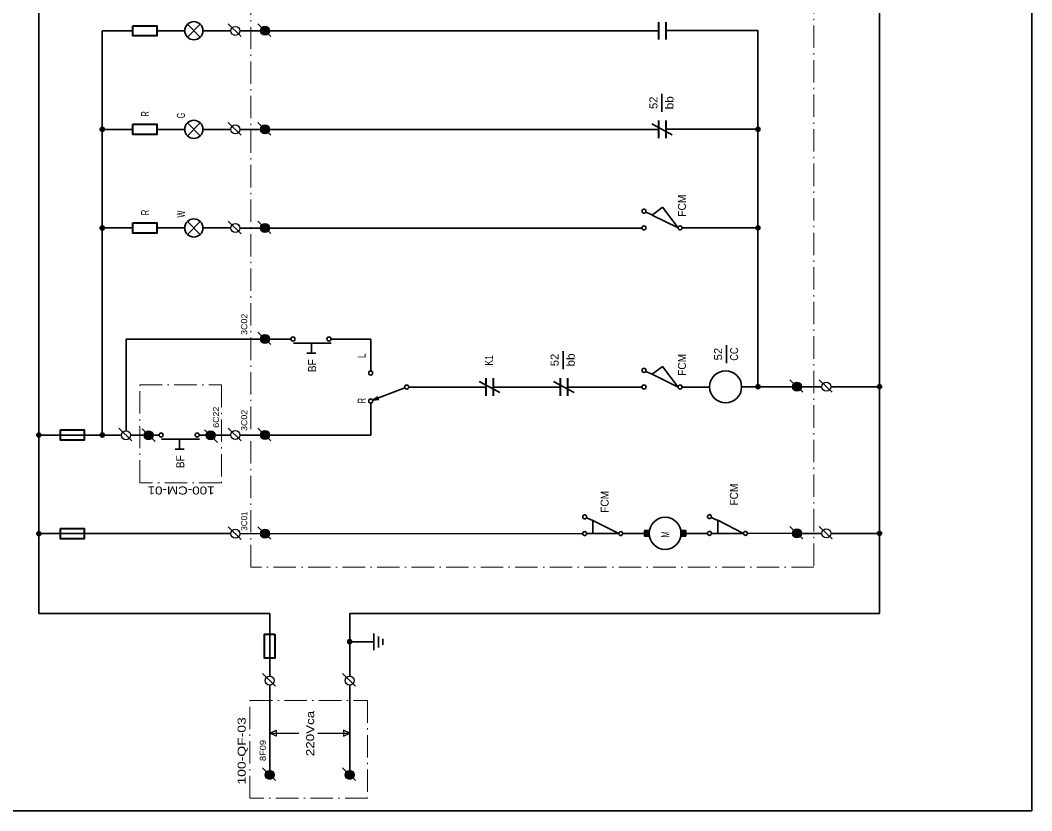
# Model space of a CAD drawing. Extents: x -4160 to -2690, y -474 to 714.
# Drawn here: x -3877.1 to -3750.8, y -166.5 to -67.8 of the extents above; entities that cross this region are included whole.
import ezdxf
from ezdxf.enums import TextEntityAlignment as Align

# ---------------------------------------------------------------- set-up
doc = ezdxf.new("R2010")
doc.units = 0
doc.header["$LTSCALE"] = 0.56
doc.linetypes.add('DOT_DASHED', pattern=[7.7, 5, -1.2, 0.3, -1.2])
for name, color, linetype, lineweight in [('1', 7, 'Continuous', 25), ('2', 7, 'Continuous', 25), ('4', 7, 'Continuous', 25), ('5', 7, 'Continuous', 35)]:
    doc.layers.add(name, color=color, linetype=linetype, lineweight=lineweight)

msp = doc.modelspace()

# ---------------------------------------------------------------- hatches: boundary and pattern name
at = {"layer": '1'}
for points in [[(-3846.5451, -69.6769, 1), (-3846.5451, -68.553, 1)], [(-3866.8755, -81.1668, 1), (-3866.8755, -81.6825, 1)], [(-3846.5451, -81.9931, 1), (-3846.5451, -80.8693, 1)], [(-3784.9703, -81.153, 1), (-3784.9703, -81.6687, 1)], [(-3866.8756, -93.483, 1), (-3866.8756, -93.9987, 1)], [(-3846.5452, -94.3094, 1), (-3846.5452, -93.1855, 1)], [(-3784.9704, -93.4692, 1), (-3784.9704, -93.9849, 1)], [(-3846.5452, -108.1702, 1), (-3846.5452, -107.0463, 1)], [(-3784.9704, -113.3048, 1), (-3784.9704, -113.8205, 1)], [(-3780.0915, -114.1247, 1), (-3780.0915, -113.0008, 1)], [(-3769.7833, -113.3048, 1), (-3769.7833, -113.8205, 1)], [(-3874.7921, -119.3374, 1), (-3874.7921, -119.8531, 1)], [(-3866.8756, -119.3374, 1), (-3866.8756, -119.8531, 1)], [(-3861.0915, -120.1947, 1), (-3861.0915, -119.0708, 1)], [(-3853.3283, -120.1947, 1), (-3853.3283, -119.0708, 1)], [(-3846.5452, -120.1638, 1), (-3846.5452, -119.0399, 1)], [(-3846.5452, -132.48, 1), (-3846.5452, -131.3562, 1)], [(-3780.0915, -132.4377, 1), (-3780.0915, -131.3139, 1)], [(-3874.7921, -131.6537, 1), (-3874.7921, -132.1694, 1)], [(-3798.5379, -132.2246), (-3798.5379, -131.5239), (-3799.1451, -131.5239), (-3799.1451, -132.2246)], [(-3794.5917, -132.2246), (-3794.5917, -131.5239), (-3793.9845, -131.5239), (-3793.9845, -132.2246)], [(-3769.7833, -131.6178, 1), (-3769.7833, -132.1335, 1)], [(-3835.9574, -145.1596, 1), (-3835.9574, -145.6753, 1)], [(-3845.9574, -162.5966, 1), (-3845.9574, -161.4728, 1)], [(-3835.9574, -162.5966, 1), (-3835.9574, -161.4728, 1)]]:
    msp.add_hatch(color=256, dxfattribs=at).paths.add_polyline_path(points)

# ---------------------------------------------------------------- linework, layer by layer
at = {"layer": '1', "lineweight": 35}
for p, q in [((-3874.7921, -141.8757), (-3874.7921, -62.7685)), ((-3769.7833, -62.7685), (-3769.7833, -141.8757)), ((-3866.8756, -119.5953), (-3866.8755, -69.1084)), ((-3866.8755, -69.1084), (-3863.0503, -69.1084)), ((-3860.0625, -69.1084), (-3856.5624, -69.1084)), ((-3854.3024, -69.1084), (-3850.8023, -69.1084)), ((-3851.1359, -68.2551), (-3849.5129, -69.8287)), ((-3849.6785, -69.1166), (-3797.3429, -69.1166)), ((-3847.4406, -68.2453), (-3845.8175, -69.8189)), ((-3796.4349, -69.0946), (-3784.9703, -69.0945)), ((-3784.9703, -113.5627), (-3784.9703, -69.0945)), ((-3796.9667, -79.2431), (-3796.9667, -77.0006)), ((-3851.1359, -80.5714), (-3849.5129, -82.145)), ((-3847.4407, -80.5616), (-3845.8176, -82.1352)), ((-3798.216, -80.7443), (-3795.6718, -82.1213)), ((-3866.8755, -81.4247), (-3863.0504, -81.4247)), ((-3860.0625, -81.4247), (-3856.5625, -81.4247)), ((-3854.3025, -81.4247), (-3850.8023, -81.4247)), ((-3849.6785, -81.4329), (-3797.3429, -81.4329)), ((-3796.4349, -81.4109), (-3784.9703, -81.4109)), ((-3798.1685, -92.1151), (-3798.9689, -91.7667)), ((-3851.136, -92.8877), (-3849.5129, -94.4613)), ((-3847.4407, -92.8779), (-3845.8177, -94.4515)), ((-3866.8755, -93.7409), (-3863.0505, -93.7409)), ((-3860.0625, -93.7409), (-3856.5625, -93.7409)), ((-3854.3025, -93.7409), (-3850.8024, -93.7409)), ((-3849.6786, -93.7491), (-3799.4429, -93.7491)), ((-3794.4439, -93.7271), (-3784.9703, -93.7271)), ((-3847.4407, -106.7387), (-3845.8177, -108.3123)), ((-3863.9005, -119.0579), (-3863.9004, -107.6099)), ((-3863.9004, -107.6099), (-3843.2997, -107.6099)), ((-3843.0023, -108.1165), (-3838.2748, -108.1165)), ((-3840.7435, -108.1165), (-3840.7435, -109.3699)), ((-3833.3419, -107.6099), (-3838.1875, -107.6099)), ((-3833.3419, -107.6099), (-3833.3419, -111.6107)), ((-3788.8891, -110.6293), (-3788.8891, -108.3868)), ((-3841.3082, -109.3699), (-3840.1789, -109.3699)), ((-3809.3105, -111.3629), (-3809.3105, -109.1203)), ((-3798.1685, -111.9947), (-3798.9689, -111.6464)), ((-3833.1089, -115.2622), (-3829.0751, -113.6971)), ((-3828.592, -113.6067), (-3818.9003, -113.6067)), ((-3819.7735, -112.9182), (-3817.2293, -114.2952)), ((-3817.9923, -113.6067), (-3809.6131, -113.6067)), ((-3810.4863, -112.9182), (-3807.9421, -114.2952)), ((-3799.4439, -113.6067), (-3808.7051, -113.6067)), ((-3794.4439, -113.6067), (-3791.0053, -113.6067)), ((-3787.0074, -113.5627), (-3780.6535, -113.5627)), ((-3780.9871, -112.6931), (-3779.364, -114.2667)), ((-3779.5295, -113.5627), (-3776.9887, -113.5627)), ((-3777.3223, -112.6931), (-3775.6993, -114.2667)), ((-3775.8649, -113.5627), (-3769.7833, -113.5627)), ((-3833.1089, -115.2622), (-3832.4629, -114.8225)), ((-3833.3419, -119.6035), (-3833.3419, -115.6027)), ((-3833.1089, -115.2622), (-3832.3354, -115.1512)), ((-3864.796, -118.7503), (-3863.1729, -120.3239)), ((-3851.1361, -118.7339), (-3849.513, -120.3075)), ((-3847.4407, -118.7323), (-3845.8177, -120.3059)), ((-3874.7921, -119.5953), (-3864.4621, -119.5953)), ((-3863.3387, -119.6035), (-3859.766, -119.6035)), ((-3861.8715, -118.8313), (-3860.2485, -120.4049)), ((-3854.7661, -119.6035), (-3850.8025, -119.6035)), ((-3852.4969, -120.5346), (-3854.12, -118.961)), ((-3849.6786, -119.6035), (-3833.3419, -119.6035)), ((-3859.4686, -120.1101), (-3854.7411, -120.1101)), ((-3856.6509, -120.1101), (-3857.5589, -120.1101)), ((-3857.2099, -120.1101), (-3857.2099, -121.3634)), ((-3857.7745, -121.3634), (-3856.6452, -121.3634)), ((-3805.5801, -130.2858), (-3806.3804, -129.9375)), ((-3789.9988, -130.2638), (-3790.7991, -129.9155)), ((-3851.136, -131.0583), (-3849.5129, -132.6319)), ((-3847.4407, -131.0485), (-3845.8177, -132.6221)), ((-3780.9871, -131.0062), (-3779.364, -132.5798)), ((-3777.3223, -131.0061), (-3775.6993, -132.5797)), ((-3874.7921, -131.9115), (-3850.8024, -131.9115)), ((-3849.6786, -131.9197), (-3806.7821, -131.8978)), ((-3805.5801, -131.8978), (-3806.3554, -131.8978)), ((-3798.5638, -131.8758), (-3801.8555, -131.8758)), ((-3794.5658, -131.8758), (-3791.2741, -131.8758)), ((-3789.9988, -131.8758), (-3790.7741, -131.8758)), ((-3786.2741, -131.8539), (-3780.6535, -131.8758)), ((-3779.5295, -131.8758), (-3776.9887, -131.8758)), ((-3775.8649, -131.8757), (-3769.7833, -131.8757)), ((-3874.7921, -141.8757), (-3845.9573, -141.8757)), ((-3845.9573, -141.8757), (-3845.9573, -149.6963)), ((-3835.9573, -141.8757), (-3835.9573, -149.6963)), ((-3835.9573, -141.8757), (-3769.7833, -141.8757)), ((-3832.9337, -146.4479), (-3832.9337, -144.387)), ((-3832.3831, -146.1329), (-3832.3831, -144.7396)), ((-3831.8035, -145.8136), (-3831.8035, -145.0589)), ((-3835.9573, -145.4175), (-3832.9337, -145.4175)), ((-3846.8529, -149.3887), (-3845.2299, -150.9623)), ((-3836.8529, -149.3887), (-3835.2299, -150.9623)), ((-3845.9574, -150.8202), (-3845.9574, -161.4727)), ((-3835.9574, -150.8202), (-3835.9574, -161.4727)), ((-3846.8529, -161.1651), (-3845.2299, -162.7387)), ((-3836.8529, -161.1651), (-3835.2299, -162.7387))]:
    msp.add_line(p, q, dxfattribs=at)
at = {"layer": '1', "lineweight": 40}
for p, q in [((-3797.3429, -70.2118), (-3797.3429, -68.0252)), ((-3796.4349, -70.2118), (-3796.4349, -68.0252)), ((-3797.3429, -82.5281), (-3797.3429, -80.3415)), ((-3796.4349, -82.5281), (-3796.4349, -80.3415)), ((-3818.9003, -114.7019), (-3818.9003, -112.5153)), ((-3817.9923, -114.7019), (-3817.9923, -112.5153)), ((-3809.6131, -114.7019), (-3809.6131, -112.5153)), ((-3808.7051, -114.7019), (-3808.7051, -112.5153))]:
    msp.add_line(p, q, dxfattribs=at)
at = {"layer": '1'}
for p, q in [((-3856.2315, -68.3093), (-3854.6333, -69.9075)), ((-3856.2315, -69.9075), (-3854.6334, -68.3094)), ((-3856.2315, -80.6256), (-3854.6334, -82.2237)), ((-3856.2315, -82.2237), (-3854.6335, -80.6257)), ((-3856.2315, -92.9419), (-3854.6335, -94.5399)), ((-3856.2315, -94.5399), (-3854.6335, -92.9419)), ((-3845.9573, -156.8151), (-3842.3215, -156.8151)), ((-3839.9376, -156.8151), (-3835.9573, -156.8151))]:
    msp.add_line(p, q, dxfattribs=at)
at = {"layer": '1', "linetype": 'DOT_DASHED', "lineweight": 13}
for points in [[(-3848.3279, -136.1027), (-3848.3279, 47.9667), (-3777.9927, 47.9667), (-3777.9927, -136.1027)], [(-3862.1888, -125.5548), (-3862.1888, -113.3493), (-3851.9577, -113.3492), (-3851.9577, -125.5548)], [(-3848.4239, -164.9458), (-3848.4239, -152.7493), (-3833.7453, -152.7493), (-3833.7453, -164.9458)]]:
    msp.add_lwpolyline(points, close=True, dxfattribs=at)
at = {"layer": '1', "lineweight": 40}
for points in [[(-3863.0503, -68.4785), (-3860.0625, -68.4785), (-3860.0625, -69.7383), (-3863.0503, -69.7383)], [(-3863.0504, -80.7948), (-3860.0625, -80.7948), (-3860.0625, -82.0545), (-3863.0504, -82.0545)], [(-3863.0505, -93.1111), (-3860.0625, -93.1111), (-3860.0625, -94.3707), (-3863.0505, -94.3707)], [(-3872.1015, -118.9655), (-3869.1136, -118.9655), (-3869.1136, -120.2251), (-3872.1015, -120.2251)], [(-3872.1015, -131.2817), (-3869.1136, -131.2817), (-3869.1136, -132.5414), (-3872.1015, -132.5414)], [(-3845.3275, -144.47), (-3845.3275, -147.4579), (-3846.5872, -147.4579), (-3846.5872, -144.47)]]:
    msp.add_lwpolyline(points, close=True, dxfattribs=at)
at = {"layer": '1', "lineweight": 35}
for points in [[(-3796.8791, -91.1477), (-3798.1857, -92.1279), (-3794.9439, -93.7271)], [(-3796.8791, -111.0273), (-3798.1857, -112.0076), (-3794.9439, -113.6067)], [(-3805.5801, -131.8978), (-3805.5801, -130.2643), (-3802.3554, -131.8978)], [(-3789.9988, -131.8758), (-3789.9988, -130.2423), (-3786.7741, -131.8758)], [(-3798.5379, -132.2246), (-3798.5379, -131.5239), (-3799.1451, -131.5239), (-3799.1451, -132.2246)], [(-3794.5917, -132.2246), (-3794.5917, -131.5239), (-3793.9845, -131.5239), (-3793.9845, -132.2246)]]:
    msp.add_lwpolyline(points, close=True, dxfattribs=at)
for points in [[(-3805.5801, -131.8978), (-3805.5801, -130.2643), (-3805.5801, -131.8978)], [(-3789.9988, -131.8758), (-3789.9988, -130.2423), (-3789.9988, -131.8758)]]:
    msp.add_lwpolyline(points, dxfattribs=at)
at = {"layer": '1'}
for points in [[(-3845.1619, -156.4372), (-3845.1619, -157.1931), (-3845.9573, -156.8151)], [(-3836.7529, -156.4371), (-3836.7529, -157.1931), (-3835.9573, -156.8151)]]:
    msp.add_lwpolyline(points, close=True, dxfattribs=at)
at = {"layer": '1', "lineweight": 35}
for centre, radius in [((-3855.4324, -69.1084), 1.13), ((-3855.4325, -81.4246), 1.13), ((-3866.8755, -81.4246), 0.2579), ((-3784.9703, -81.4108), 0.2579), ((-3799.1939, -91.6435), 0.25), ((-3866.8756, -93.7409), 0.2579), ((-3855.4325, -93.7409), 1.13), ((-3799.1939, -93.7271), 0.25), ((-3794.694, -93.7271), 0.25), ((-3784.9704, -93.727), 0.2579), ((-3843.0497, -107.6099), 0.25), ((-3838.5497, -107.6099), 0.25), ((-3833.3419, -111.8608), 0.25), ((-3799.1939, -111.5231), 0.25), ((-3789.0064, -113.5847), 1.999), ((-3828.842, -113.6067), 0.25), ((-3799.1939, -113.6067), 0.25), ((-3794.694, -113.6067), 0.25), ((-3784.9704, -113.5627), 0.2579), ((-3769.7833, -113.5627), 0.2579), ((-3833.3419, -115.3526), 0.25), ((-3874.7921, -119.5953), 0.2579), ((-3866.8756, -119.5953), 0.2579), ((-3859.516, -119.6035), 0.25), ((-3855.0161, -119.6035), 0.25), ((-3806.6054, -129.8142), 0.25), ((-3796.5648, -131.8758), 1.999), ((-3791.0241, -129.7922), 0.25), ((-3874.7921, -131.9115), 0.2579), ((-3806.6054, -131.8978), 0.25), ((-3802.1055, -131.8978), 0.25), ((-3791.0242, -131.8758), 0.25), ((-3786.5242, -131.8758), 0.25), ((-3769.7833, -131.8757), 0.2579), ((-3835.9574, -145.4175), 0.2579)]:
    msp.add_circle(centre, radius, dxfattribs=at)
at = {"layer": '1'}
for centre in [(-3850.2404, -69.1248), (-3846.5451, -69.115), (-3850.2404, -81.441), (-3846.5451, -81.4312), (-3850.2405, -93.7572), (-3846.5452, -93.7475), (-3846.5452, -107.6082), (-3780.0915, -113.5628), (-3776.4268, -113.5627), (-3863.9004, -119.6198), (-3861.0915, -119.6328), (-3853.3283, -119.6328), (-3850.2405, -119.6035), (-3846.5452, -119.6018), (-3850.2405, -131.9279), (-3846.5452, -131.9181), (-3780.0915, -131.8758), (-3776.4268, -131.8758), (-3845.9574, -150.2583), (-3835.9574, -150.2583), (-3845.9574, -162.0347), (-3835.9574, -162.0347)]:
    msp.add_circle(centre, 0.5619, dxfattribs=at)
at = {"layer": '5'}
msp.add_lwpolyline([(-3924.7642, -166.52), (-3924.7642, 86.48), (-3750.7642, 86.48), (-3750.7642, -166.52)], close=True, dxfattribs=at)

# ---------------------------------------------------------------- texts
at = {"layer": '1'}
for s, height, width, p in [('52', 1, 1.05, (-3797.5236, -78.1059)), ('bb', 1, 1.1, (-3795.5236, -78.106)), ('R', 1, 0.65, (-3861.0193, -79.4988)), ('G', 1, 0.6, (-3856.5523, -79.6956)), ('R', 1, 0.65, (-3861.0193, -91.815)), ('W', 1, 0.55, (-3856.5523, -92.0119)), ('3C02', 0.75, 1.1, (-3848.7643, -105.7736)), ('L', 1, 0.8, (-3833.9654, -109.702)), ('K1', 1, 0.8, (-3818.0811, -110.2798)), ('52', 1, 1.05, (-3809.8673, -110.2257)), ('bb', 1, 1.1, (-3807.8673, -110.2257)), ('52', 1, 1.05, (-3789.446, -109.4921)), ('CC', 1, 0.85, (-3787.446, -109.4921)), ('BF', 1, 0.95, (-3840.1593, -110.9447)), ('6C22', 0.75, 1.1, (-3852.2857, -117.3762)), ('R', 1, 0.65, (-3833.9654, -115.3116)), ('3C02', 0.75, 1.1, (-3848.7643, -117.7672)), ('BF', 1, 0.95, (-3856.6257, -122.9382)), ('220Vca', 1, 1.25, (-3840.3999, -156.87)), ('8F09', 0.75, 1.15, (-3846.4391, -158.9981))]:
    msp.add_text(s, height=height, rotation=90, dxfattribs=dict(at, width=width)).set_placement(p, align=Align.CENTER)
msp.add_text('3C01', height=0.75, rotation=90, dxfattribs=at).set_placement((-3848.7643, -130.3448), align=Align.CENTER)
at = {"layer": '2', "width": 0.95}
for p in [(-3793.9601, -90.9551), (-3793.9601, -110.8348), (-3787.4695, -127.0363), (-3803.6173, -127.9464)]:
    msp.add_text('FCM', height=1, rotation=90, dxfattribs=at).set_placement(p, align=Align.CENTER)
at = {"layer": '4'}
for s, height, rotation, width, p in [('100-CM-01', 0.9999, 180, 1.25, (-3857.0267, -126.0241)), ('M', 1, 90, 0.65, (-3796.0479, -132.0071)), ('100-QF-03', 0.9999, 90, 1.3, (-3848.9593, -159.0421))]:
    msp.add_text(s, height=height, rotation=rotation, dxfattribs=dict(at, width=width)).set_placement(p, align=Align.CENTER)

doc.saveas('drawing.dxf')
